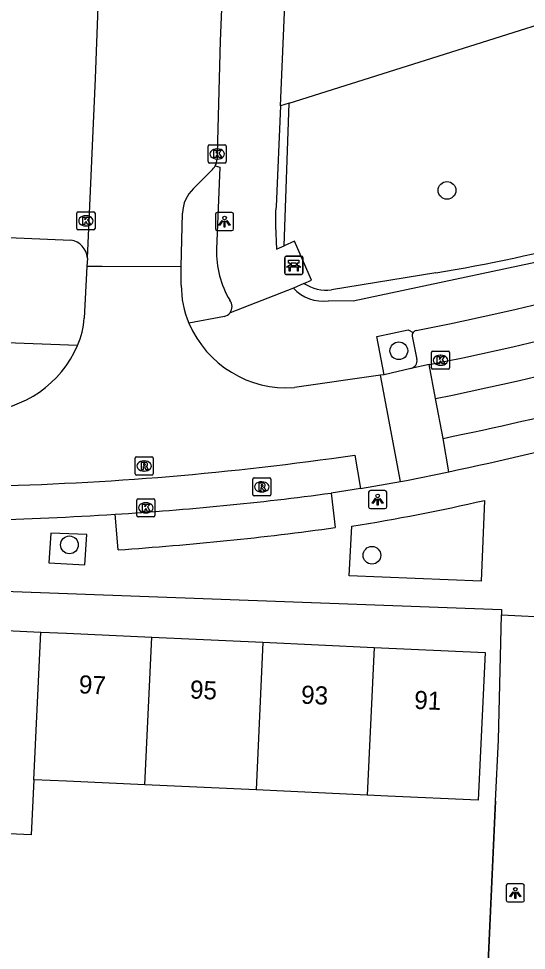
# Model space of a CAD drawing. Extents: x 161355 to 162026, y 386504 to 387459.
# Drawn here: x 161497.3 to 161525.4, y 386792.5 to 386843.9 of the extents above; entities that cross this region are included whole.
import ezdxf

# ---------------------------------------------------------------- set-up
doc = ezdxf.new("R2010")
doc.units = 0
for name, color, linetype in [('IMGEO_Bank', 7, 'Continuous'), ('IMGEO_Boom', 7, 'Continuous'), ('IMGEO_Groenvoorziening', 7, 'Continuous'), ('IMGEO_Haag', 7, 'Continuous'), ('IMGEO_Kolk', 7, 'Continuous'), ('IMGEO_Lichtpunt', 7, 'Continuous'), ('IMGEO_Muur', 7, 'Continuous'), ('IMGEO_Pand', 7, 'Continuous'), ('IMGEO_Pand_nummerreeks', 7, 'Continuous'), ('IMGEO_Parkeervlak_open', 7, 'Continuous'), ('IMGEO_Rijbaan_lokaal_gesloten', 7, 'Continuous'), ('IMGEO_Rijbaan_lokaal_open', 7, 'Continuous'), ('IMGEO_Rioolput', 7, 'Continuous'), ('IMGEO_Voetpad_open', 7, 'Continuous')]:
    doc.layers.add(name, color=color, linetype=linetype)

msp = doc.modelspace()

# ---------------------------------------------------------------- linework, layer by layer
at = {"layer": 'IMGEO_Bank'}
for p, q in [((161512.04, 386829.902), (161512.04, 386830.743)), ((161512.04, 386830.743), (161512.04, 386829.902)), ((161512.115, 386830.827), (161512.956, 386830.827)), ((161512.956, 386830.827), (161512.115, 386830.827)), ((161513.04, 386830.752), (161513.04, 386829.911)), ((161513.04, 386829.911), (161513.04, 386830.752)), ((161512.737, 386830.225), (161512.344, 386830.225)), ((161512.349, 386830.333), (161512.349, 386830.439)), ((161512.393, 386830.439), (161512.393, 386830.333)), ((161512.681, 386830.445), (161512.399, 386830.445)), ((161512.399, 386830.327), (161512.681, 386830.327)), ((161512.687, 386830.333), (161512.687, 386830.439)), ((161512.731, 386830.439), (161512.731, 386830.333)), ((161512.965, 386829.827), (161512.124, 386829.827)), ((161512.124, 386829.827), (161512.965, 386829.827))]:
    msp.add_line(p, q, dxfattribs=at)
for points in [[(161512.343, 386830.445), (161512.257, 386830.445), (161512.257, 386830.606), (161512.82, 386830.606), (161512.82, 386830.445), (161512.737, 386830.445)], [(161512.287, 386830.225), (161512.145, 386830.225), (161512.257, 386830.327), (161512.343, 386830.327)], [(161512.337, 386830.218), (161512.337, 386830.011), (161512.294, 386830.011), (161512.294, 386830.218)], [(161512.737, 386830.327), (161512.82, 386830.327), (161512.932, 386830.225), (161512.793, 386830.225)], [(161512.787, 386830.218), (161512.787, 386830.011), (161512.743, 386830.011), (161512.743, 386830.218)]]:
    msp.add_lwpolyline(points, dxfattribs=at)
for centre, radius, start, end in [((161512.118, 386830.749), 0.0779, 92.4484, 184.2845), ((161512.118, 386830.749), 0.0779, 92.4484, 184.2845), ((161512.962, 386830.749), 0.0779, 2.4484, 94.2845), ((161512.962, 386830.749), 0.0779, 2.4484, 94.2845), ((161512.287, 386830.218), 0.00671, 2.8957, 87.1043), ((161512.344, 386830.218), 0.00671, 92.8957, 177.1043), ((161512.342, 386830.438), 0.00671, 2.8957, 87.1043), ((161512.342, 386830.334), 0.00671, 272.8957, 357.1043), ((161512.399, 386830.438), 0.00671, 92.8957, 177.1043), ((161512.399, 386830.334), 0.00671, 182.8957, 267.1043), ((161512.681, 386830.438), 0.00671, 2.8957, 87.1043), ((161512.681, 386830.334), 0.00671, 272.8957, 357.1043), ((161512.738, 386830.438), 0.00671, 92.8957, 177.1043), ((161512.738, 386830.334), 0.00671, 182.8957, 267.1043), ((161512.736, 386830.218), 0.00671, 2.8957, 87.1043), ((161512.793, 386830.218), 0.00671, 92.8957, 177.1043), ((161512.118, 386829.905), 0.0779, 182.4484, 274.2845), ((161512.118, 386829.905), 0.0779, 182.4484, 274.2845), ((161512.962, 386829.905), 0.0779, 272.4484, 4.2845), ((161512.962, 386829.905), 0.0779, 272.4484, 4.2845)]:
    msp.add_arc(centre, radius, start, end, dxfattribs=at)
at = {"layer": 'IMGEO_Boom'}
for centre in [(161520.999, 386834.464), (161518.34, 386825.613), (161500.153, 386814.901), (161516.856, 386814.324)]:
    msp.add_circle(centre, 0.489, dxfattribs=at)
at = {"layer": 'IMGEO_Groenvoorziening'}
msp.add_lwpolyline([(161512.278, 386839.281), (161538.761, 386847.649), (161539.899, 386848.027)], dxfattribs=at)
at = {"layer": 'IMGEO_Haag'}
for points in [[(161512.278, 386839.281), (161511.8, 386839.13)], [(161512.001, 386831.405), (161512.278, 386839.281)], [(161520.374, 386829.914), (161514.63, 386828.974)]]:
    msp.add_lwpolyline(points, dxfattribs=at)
for centre, radius, start, end in [((161506.753, 386913.447), 84.637, 279.26136, 285.20102), ((161514.367, 386831.329), 2.369, 237.7468, 276.3626)]:
    msp.add_arc(centre, radius, start, end, dxfattribs=at)
at = {"layer": 'IMGEO_Kolk'}
for p, q in [((161507.814, 386836.05), (161507.814, 386836.902)), ((161507.889, 386836.976), (161508.741, 386836.976)), ((161508.302, 386836.756), (161508.327, 386836.756)), ((161508.815, 386836.902), (161508.815, 386836.05)), ((161508.741, 386835.976), (161507.889, 386835.976)), ((161508.325, 386836.196), (161508.3, 386836.196)), ((161500.565, 386832.357), (161500.565, 386833.209)), ((161500.64, 386833.283), (161501.492, 386833.283)), ((161501.566, 386833.209), (161501.566, 386832.357)), ((161501.053, 386833.063), (161501.078, 386833.063)), ((161501.492, 386832.283), (161500.64, 386832.283)), ((161501.076, 386832.503), (161501.051, 386832.503)), ((161520.138, 386824.663), (161520.138, 386825.515)), ((161520.213, 386825.589), (161521.065, 386825.589)), ((161521.139, 386825.515), (161521.139, 386824.663)), ((161520.626, 386825.369), (161520.651, 386825.369)), ((161521.065, 386824.589), (161520.213, 386824.589)), ((161520.649, 386824.809), (161520.624, 386824.809)), ((161503.87, 386816.519), (161503.87, 386817.371)), ((161503.945, 386817.445), (161504.797, 386817.445)), ((161504.358, 386817.225), (161504.383, 386817.225)), ((161504.871, 386817.371), (161504.871, 386816.519)), ((161504.797, 386816.445), (161503.945, 386816.445)), ((161504.381, 386816.665), (161504.356, 386816.665))]:
    msp.add_line(p, q, dxfattribs=at)
for points in [[(161507.814, 386836.05), (161507.814, 386836.902)], [(161507.889, 386836.976), (161508.741, 386836.976)], [(161508.815, 386836.902), (161508.815, 386836.05)], [(161508.135, 386836.676), (161508.258, 386836.676), (161508.258, 386836.525), (161508.388, 386836.676), (161508.552, 386836.676), (161508.406, 386836.525), (161508.559, 386836.276), (161508.407, 386836.276), (161508.322, 386836.44), (161508.258, 386836.373), (161508.258, 386836.276), (161508.135, 386836.276), (161508.135, 386836.676)], [(161508.741, 386835.976), (161507.889, 386835.976)], [(161500.565, 386832.357), (161500.565, 386833.209)], [(161500.64, 386833.283), (161501.492, 386833.283)], [(161501.566, 386833.209), (161501.566, 386832.357)], [(161500.886, 386832.983), (161501.009, 386832.983), (161501.009, 386832.832), (161501.139, 386832.983), (161501.303, 386832.983), (161501.157, 386832.832), (161501.31, 386832.583), (161501.158, 386832.583), (161501.073, 386832.747), (161501.009, 386832.68), (161501.009, 386832.583), (161500.886, 386832.583), (161500.886, 386832.983)], [(161501.492, 386832.283), (161500.64, 386832.283)], [(161520.138, 386824.663), (161520.138, 386825.515)], [(161520.213, 386825.589), (161521.065, 386825.589)], [(161521.139, 386825.515), (161521.139, 386824.663)], [(161520.459, 386825.289), (161520.582, 386825.289), (161520.582, 386825.138), (161520.712, 386825.289), (161520.876, 386825.289), (161520.73, 386825.138), (161520.883, 386824.889), (161520.731, 386824.889), (161520.646, 386825.053), (161520.582, 386824.986), (161520.582, 386824.889), (161520.459, 386824.889), (161520.459, 386825.289)], [(161521.065, 386824.589), (161520.213, 386824.589)], [(161503.87, 386816.519), (161503.87, 386817.371)], [(161503.945, 386817.445), (161504.797, 386817.445)], [(161504.871, 386817.371), (161504.871, 386816.519)], [(161504.191, 386817.145), (161504.314, 386817.145), (161504.314, 386816.994), (161504.444, 386817.145), (161504.608, 386817.145), (161504.462, 386816.994), (161504.615, 386816.745), (161504.463, 386816.745), (161504.378, 386816.909), (161504.314, 386816.842), (161504.314, 386816.745), (161504.191, 386816.745), (161504.191, 386817.145)], [(161504.797, 386816.445), (161503.945, 386816.445)]]:
    msp.add_lwpolyline(points, dxfattribs=at)
for centre, start, end in [((161507.891, 386836.9), 91.552, 178.448), ((161507.891, 386836.9), 91.552, 178.448), ((161508.739, 386836.9), 1.552, 88.448), ((161508.739, 386836.9), 1.552, 88.448), ((161507.891, 386836.052), 181.552, 268.448), ((161507.891, 386836.052), 181.552, 268.448), ((161508.739, 386836.052), 271.552, 358.448), ((161508.739, 386836.052), 271.552, 358.448), ((161500.642, 386833.207), 91.552, 178.448), ((161500.642, 386833.207), 91.552, 178.448), ((161501.49, 386833.207), 1.552, 88.448), ((161501.49, 386833.207), 1.552, 88.448), ((161500.642, 386832.359), 181.552, 268.448), ((161500.642, 386832.359), 181.552, 268.448), ((161501.49, 386832.359), 271.552, 358.448), ((161501.49, 386832.359), 271.552, 358.448), ((161520.215, 386825.513), 91.552, 178.448), ((161520.215, 386825.513), 91.552, 178.448), ((161521.063, 386825.513), 1.552, 88.448), ((161521.063, 386825.513), 1.552, 88.448), ((161520.215, 386824.665), 181.552, 268.448), ((161520.215, 386824.665), 181.552, 268.448), ((161521.063, 386824.665), 271.552, 358.448), ((161521.063, 386824.665), 271.552, 358.448), ((161503.947, 386817.369), 91.552, 178.448), ((161503.947, 386817.369), 91.552, 178.448), ((161504.795, 386817.369), 1.552, 88.448), ((161504.795, 386817.369), 1.552, 88.448), ((161503.947, 386816.521), 181.552, 268.448), ((161503.947, 386816.521), 181.552, 268.448), ((161504.795, 386816.521), 271.552, 358.448), ((161504.795, 386816.521), 271.552, 358.448)]:
    msp.add_arc(centre, 0.0765, start, end, dxfattribs=at)
for centre, major_axis, ratio, start_param, end_param in [((161508.301, 386836.476), (-0.387, 0.002), 0.722429, 4.712389, 7.853982), ((161508.326, 386836.476), (-0.39, 0.002), 0.717154, 1.570796, 4.712389), ((161501.052, 386832.783), (-0.387, 0.002), 0.722429, 4.712389, 7.853982), ((161501.077, 386832.783), (-0.39, 0.002), 0.717154, 1.570796, 4.712389), ((161520.625, 386825.089), (-0.387, 0.002), 0.722429, 4.712389, 7.853982), ((161520.65, 386825.089), (-0.39, 0.002), 0.717154, 1.570796, 4.712389), ((161504.357, 386816.945), (-0.387, 0.002), 0.722429, 4.712389, 7.853982), ((161504.382, 386816.945), (-0.39, 0.002), 0.717154, 1.570796, 4.712389)]:
    msp.add_ellipse(centre, major_axis=major_axis, ratio=ratio, start_param=start_param, end_param=end_param, dxfattribs=at)
at = {"layer": 'IMGEO_Lichtpunt'}
for p, q in [((161509.12, 386833.241), (161508.312, 386833.241)), ((161509.12, 386833.241), (161508.312, 386833.241)), ((161508.218, 386833.146), (161508.218, 386832.339)), ((161508.218, 386833.146), (161508.218, 386832.339)), ((161509.214, 386832.339), (161509.214, 386833.146)), ((161509.214, 386832.339), (161509.214, 386833.146)), ((161508.312, 386832.245), (161509.12, 386832.245)), ((161508.312, 386832.245), (161509.12, 386832.245)), ((161516.673, 386817.805), (161516.673, 386816.998)), ((161516.673, 386817.805), (161516.673, 386816.998)), ((161517.575, 386817.9), (161516.767, 386817.9)), ((161517.575, 386817.9), (161516.767, 386817.9)), ((161517.669, 386816.998), (161517.669, 386817.805)), ((161517.669, 386816.998), (161517.669, 386817.805)), ((161516.767, 386816.904), (161517.575, 386816.904)), ((161516.767, 386816.904), (161517.575, 386816.904)), ((161525.175, 386796.188), (161524.367, 386796.188)), ((161525.175, 386796.188), (161524.367, 386796.188)), ((161524.273, 386796.093), (161524.273, 386795.286)), ((161524.273, 386796.093), (161524.273, 386795.286)), ((161525.269, 386795.286), (161525.269, 386796.093)), ((161525.269, 386795.286), (161525.269, 386796.093)), ((161524.367, 386795.192), (161525.175, 386795.192)), ((161524.367, 386795.192), (161525.175, 386795.192))]:
    msp.add_line(p, q, dxfattribs=at)
for points in [[(161508.592, 386832.81), (161508.631, 386832.782), (161508.443, 386832.52), (161508.405, 386832.547), (161508.592, 386832.81)], [(161508.694, 386832.762), (161508.741, 386832.762), (161508.741, 386832.44), (161508.694, 386832.44), (161508.694, 386832.762)], [(161508.804, 386832.782), (161508.842, 386832.809), (161509.029, 386832.547), (161508.99, 386832.519), (161508.804, 386832.782)], [(161517.047, 386817.469), (161517.086, 386817.441), (161516.898, 386817.179), (161516.86, 386817.206), (161517.047, 386817.469)], [(161517.149, 386817.421), (161517.196, 386817.421), (161517.196, 386817.099), (161517.149, 386817.099), (161517.149, 386817.421)], [(161517.259, 386817.441), (161517.297, 386817.468), (161517.484, 386817.206), (161517.445, 386817.178), (161517.259, 386817.441)], [(161524.647, 386795.757), (161524.686, 386795.729), (161524.498, 386795.467), (161524.46, 386795.494), (161524.647, 386795.757)], [(161524.749, 386795.709), (161524.796, 386795.709), (161524.796, 386795.387), (161524.749, 386795.387), (161524.749, 386795.709)], [(161524.859, 386795.729), (161524.897, 386795.756), (161525.084, 386795.494), (161525.045, 386795.466), (161524.859, 386795.729)]]:
    msp.add_lwpolyline(points, dxfattribs=at)
for centre in [(161508.717, 386832.944), (161517.172, 386817.603), (161524.772, 386795.891)]:
    msp.add_circle(centre, 0.0994, dxfattribs=at)
for centre, start, end in [((161508.312, 386833.146), 90, 180), ((161508.312, 386833.146), 90, 180), ((161509.12, 386833.146), 0, 90), ((161509.12, 386833.146), 0, 90), ((161508.312, 386832.339), 180, 270), ((161508.312, 386832.339), 180, 270), ((161509.12, 386832.339), 270, 0), ((161509.12, 386832.339), 270, 360), ((161516.767, 386817.805), 90, 180), ((161516.767, 386817.805), 90, 180), ((161517.575, 386817.805), 0, 90), ((161517.575, 386817.805), 0, 90), ((161516.767, 386816.998), 180, 270), ((161516.767, 386816.998), 180, 270), ((161517.575, 386816.998), 270, 0), ((161517.575, 386816.998), 270, 360), ((161524.367, 386796.093), 90, 180), ((161524.367, 386796.093), 90, 180), ((161525.175, 386796.093), 0, 90), ((161525.175, 386796.093), 0, 90), ((161524.367, 386795.286), 180, 270), ((161524.367, 386795.286), 180, 270), ((161525.175, 386795.286), 270, 0), ((161525.175, 386795.286), 270, 360)]:
    msp.add_arc(centre, 0.0946, start, end, dxfattribs=at)
at = {"layer": 'IMGEO_Muur'}
msp.add_lwpolyline([(161523.683, 386800.76), (161523.16, 386789.429)], dxfattribs=at)
at = {"layer": 'IMGEO_Pand'}
for points in [[(161492.43, 386810.375), (161498.566, 386810.091)], [(161498.189, 386801.939), (161498.566, 386810.091)], [(161498.566, 386810.091), (161500, 386810.025), (161504.702, 386809.807)], [(161504.325, 386801.655), (161504.702, 386809.807)], [(161504.702, 386809.807), (161510.838, 386809.524)], [(161510.838, 386809.524), (161510.461, 386801.372)], [(161510.838, 386809.524), (161516.974, 386809.24)], [(161516.974, 386809.24), (161523.106, 386808.956), (161522.729, 386800.804), (161517.735, 386801.035), (161516.597, 386801.088)], [(161516.974, 386809.24), (161516.597, 386801.088)], [(161498.189, 386801.939), (161498.048, 386798.898), (161491.912, 386799.181)], [(161504.325, 386801.655), (161500, 386801.855), (161498.189, 386801.939)], [(161510.461, 386801.372), (161504.325, 386801.655)], [(161516.597, 386801.088), (161510.461, 386801.372)]]:
    msp.add_lwpolyline(points, dxfattribs=at)
at = {"layer": 'IMGEO_Parkeervlak_open'}
for points in [[(161495.485, 386831.914), (161500.23, 386831.711)], [(161519.079, 386826.412), (161519.342, 386825.137)]]:
    msp.add_lwpolyline(points, dxfattribs=at)
for centre, radius, start, end in [((161500.105, 386830.679), 1.039, 2.9742, 83.0884), ((161519.36, 386826.453), 0.283, 144.7696, 188.2177), ((161518.897, 386825.075), 0.449, 284.2793, 7.916)]:
    msp.add_arc(centre, radius, start, end, dxfattribs=at)
at = {"layer": 'IMGEO_Rijbaan_lokaal_gesloten'}
for points in [[(161520.368, 386822.982), (161520.018, 386824.846)], [(161521.099, 386818.935), (161520.791, 386820.779)], [(161516.217, 386818.005), (161514.61, 386817.76)]]:
    msp.add_lwpolyline(points, dxfattribs=at)
for centre, radius, start, end in [((161488.255, 386984.249), 162.536, 281.2692, 291.90897), ((161488.231, 386983.377), 163.583, 281.3297, 291.94879), ((161485.711, 386992.759), 175.521, 281.5288, 287.31954), ((161480.452, 387011.97), 197.268, 281.89109, 287.15674), ((161492.314, 386983.601), 167.333, 273.54943, 277.65689), ((161490.303, 387016.248), 200.042, 271.44792, 273.54546)]:
    msp.add_arc(centre, radius, start, end, dxfattribs=at)
at = {"layer": 'IMGEO_Rijbaan_lokaal_open'}
for points in [[(161501.143, 386830.733), (161501.602, 386840.641), (161502.894, 386875.753)], [(161508.658, 386847.12), (161508.474, 386842.71), (161508.315, 386836.476), (161508.312, 386836.198)], [(161506.999, 386834.57), (161508.002, 386835.57)], [(161506.315, 386830.237), (161506.39, 386833.21)], [(161501.143, 386830.733), (161501.115, 386830.263)], [(161501.115, 386830.263), (161500.973, 386827.416)], [(161506.315, 386830.237), (161501.963, 386830.261), (161501.115, 386830.263)], [(161506.329, 386829.238), (161506.315, 386830.237)], [(161519.008, 386824.64), (161517.535, 386824.294)], [(161520.018, 386824.846), (161519.008, 386824.64)], [(161517.334, 386824.272), (161512.575, 386823.583)], [(161517.535, 386824.294), (161517.334, 386824.272)], [(161518.426, 386818.391), (161517.334, 386824.272)], [(161520.791, 386820.779), (161520.368, 386822.982)], [(161515.906, 386819.854), (161516.217, 386818.005)], [(161518.426, 386818.391), (161518.758, 386818.449), (161521.099, 386818.935)], [(161516.217, 386818.005), (161518.426, 386818.391)]]:
    msp.add_lwpolyline(points, dxfattribs=at)
for centre, radius, start, end in [((161507.411, 386836.25), 0.901, 310.9812, 331.9179), ((161507.408, 386836.255), 0.906, 331.7724, 356.4182), ((161508.41, 386833.122), 2.022, 134.2553, 177.4996), ((161511.634, 386829.204), 5.305, 179.6378, 202.982), ((161496.689, 386827.659), 4.291, 335.7751, 356.7571), ((161512.15, 386829.439), 5.872, 203.1271, 274.1531), ((161495.009, 386828.348), 6.106, 273.2685, 336.3408), ((161491.827, 386984.539), 166.436, 271.22458, 278.31842)]:
    msp.add_arc(centre, radius, start, end, dxfattribs=at)
at = {"layer": 'IMGEO_Rioolput'}
for p, q in [((161503.776, 386818.829), (161503.776, 386819.681)), ((161503.851, 386819.755), (161504.703, 386819.755)), ((161504.264, 386819.535), (161504.289, 386819.535)), ((161504.777, 386819.681), (161504.777, 386818.829)), ((161504.703, 386818.755), (161503.851, 386818.755)), ((161504.287, 386818.975), (161504.262, 386818.975)), ((161510.272, 386817.674), (161510.272, 386818.526)), ((161510.347, 386818.6), (161511.199, 386818.6)), ((161510.76, 386818.38), (161510.785, 386818.38)), ((161511.273, 386818.526), (161511.273, 386817.674)), ((161510.783, 386817.82), (161510.758, 386817.82)), ((161511.199, 386817.6), (161510.347, 386817.6))]:
    msp.add_line(p, q, dxfattribs=at)
for points in [[(161503.776, 386818.829), (161503.776, 386819.681)], [(161503.851, 386819.755), (161504.703, 386819.755)], [(161504.365, 386819.453), (161504.113, 386819.455), (161504.113, 386819.055)], [(161504.291, 386819.374), (161504.237, 386819.374), (161504.237, 386819.293)], [(161504.237, 386819.293), (161504.289, 386819.293)], [(161504.777, 386819.681), (161504.777, 386818.829)], [(161504.703, 386818.755), (161503.851, 386818.755)], [(161504.113, 386819.055), (161504.237, 386819.055), (161504.237, 386819.217), (161504.248, 386819.217)], [(161504.295, 386819.188), (161504.366, 386819.055), (161504.506, 386819.055), (161504.441, 386819.181)], [(161510.272, 386817.674), (161510.272, 386818.526)], [(161510.347, 386818.6), (161511.199, 386818.6)], [(161510.861, 386818.298), (161510.609, 386818.3), (161510.609, 386817.9)], [(161511.273, 386818.526), (161511.273, 386817.674)], [(161510.609, 386817.9), (161510.733, 386817.9), (161510.733, 386818.062), (161510.744, 386818.062)], [(161510.787, 386818.219), (161510.733, 386818.219), (161510.733, 386818.138)], [(161510.733, 386818.138), (161510.785, 386818.138)], [(161510.791, 386818.033), (161510.862, 386817.9), (161511.002, 386817.9), (161510.937, 386818.026)], [(161511.199, 386817.6), (161510.347, 386817.6)]]:
    msp.add_lwpolyline(points, dxfattribs=at)
for centre, radius, start, end in [((161503.853, 386819.679), 0.0765, 91.552, 178.448), ((161503.853, 386819.679), 0.0765, 91.552, 178.448), ((161504.273, 386819.482), 0.19, 274.7715, 282.9687), ((161504.297, 386819.278), 0.0964, 77.0061, 93.1865), ((161504.311, 386819.335), 0.0378, 276.6634, 79.6772), ((161504.364, 386819.343), 0.109, 350.3612, 89.416), ((161504.362, 386819.343), 0.112, 277.5842, 350.9817), ((161504.701, 386819.679), 0.0765, 1.552, 88.448), ((161504.701, 386819.679), 0.0765, 1.552, 88.448), ((161503.853, 386818.831), 0.0765, 181.552, 268.448), ((161503.853, 386818.831), 0.0765, 181.552, 268.448), ((161504.247, 386819.164), 0.0533, 26.0293, 88.6989), ((161504.346, 386819.128), 0.108, 29.5134, 73.7905), ((161504.701, 386818.831), 0.0765, 271.552, 358.448), ((161504.701, 386818.831), 0.0765, 271.552, 358.448), ((161510.349, 386818.524), 0.0765, 91.552, 178.448), ((161510.349, 386818.524), 0.0765, 91.552, 178.448), ((161510.86, 386818.188), 0.109, 350.3612, 89.416), ((161511.197, 386818.524), 0.0765, 1.552, 88.448), ((161511.197, 386818.524), 0.0765, 1.552, 88.448), ((161510.743, 386818.009), 0.0533, 26.0293, 88.6989), ((161510.769, 386818.327), 0.19, 274.7715, 282.9687), ((161510.793, 386818.123), 0.0964, 77.0061, 93.1865), ((161510.807, 386818.18), 0.0378, 276.6634, 79.6772), ((161510.858, 386818.188), 0.112, 277.5842, 350.9817), ((161510.842, 386817.973), 0.108, 29.5134, 73.7905), ((161510.349, 386817.676), 0.0765, 181.552, 268.448), ((161510.349, 386817.676), 0.0765, 181.552, 268.448), ((161511.197, 386817.676), 0.0765, 271.552, 358.448), ((161511.197, 386817.676), 0.0765, 271.552, 358.448)]:
    msp.add_arc(centre, radius, start, end, dxfattribs=at)
for centre, major_axis, ratio, start_param, end_param in [((161504.263, 386819.255), (-0.387, 0.002), 0.722429, 4.712389, 7.853982), ((161504.288, 386819.255), (-0.39, 0.002), 0.717154, 1.570796, 4.712389), ((161510.759, 386818.1), (-0.387, 0.002), 0.722429, 4.712389, 7.853982), ((161510.784, 386818.1), (-0.39, 0.002), 0.717154, 1.570796, 4.712389)]:
    msp.add_ellipse(centre, major_axis=major_axis, ratio=ratio, start_param=start_param, end_param=end_param, dxfattribs=at)
at = {"layer": 'IMGEO_Voetpad_open'}
for points in [[(161511.8, 386839.13), (161513.476, 386878.267)], [(161545.191, 386839.884), (161543.789, 386836.438), (161541.337, 386835.451), (161537.295, 386833.825), (161536.546, 386833.523), (161529.161, 386831.19), (161515.819, 386828.343), (161514.452, 386828.372)], [(161511.8, 386839.13), (161511.562, 386833.581)], [(161508.206, 386835.826), (161508.464, 386835.753), (161508.265, 386831.216)], [(161511.539, 386832.502), (161511.587, 386831.224), (161511.756, 386831.298), (161512.001, 386831.405)], [(161513.103, 386829.325), (161513.523, 386829.505), (161512.578, 386831.657), (161512.001, 386831.405)], [(161512.522, 386829.076), (161509.02, 386827.712)], [(161513.103, 386829.325), (161512.522, 386829.076)], [(161508.706, 386827.502), (161506.75, 386827.133)], [(161517.535, 386824.294), (161517.122, 386826.408), (161518.848, 386826.777), (161519.128, 386826.616)], [(161500.602, 386825.898), (161495.677, 386826.081)], [(161514.61, 386817.76), (161514.833, 386815.853)], [(161523.061, 386817.353), (161522.888, 386812.892), (161515.592, 386813.19), (161515.738, 386815.931)], [(161502.851, 386814.628), (161502.674, 386816.589)], [(161501.013, 386813.794), (161501.109, 386815.467), (161499.12, 386815.552), (161499.016, 386813.902), (161501.013, 386813.794)], [(161492.529, 386812.499), (161524.007, 386811.339), (161524, 386811.032)], [(161523.04, 386786.822), (161523.16, 386789.429), (161523.683, 386800.76), (161523.839, 386804.137), (161524, 386811.032)], [(161524, 386811.032), (161526.977, 386810.897)]]:
    msp.add_lwpolyline(points, dxfattribs=at)
for centre, radius, start, end in [((161489.01, 386981.291), 157.5, 281.08766, 292.05075), ((161517.846, 386832.907), 6.32, 173.8805, 183.6772), ((161513.72, 386831.15), 5.456, 179.304, 210.3032), ((161514.149, 386830.539), 2.188, 221.9545, 277.9649), ((161508.567, 386828.048), 0.564, 323.4162, 38.2566), ((161508.566, 386828.05), 0.566, 284.2771, 323.2714), ((161519.367, 386826.446), 0.293, 103.325, 144.5178), ((161498.28, 386925.403), 110.855, 279.06092, 282.91726), ((161491.142, 386988.37), 174.136, 273.85556, 277.81933)]:
    msp.add_arc(centre, radius, start, end, dxfattribs=at)

# ---------------------------------------------------------------- texts
at = {"layer": 'IMGEO_Pand_nummerreeks'}
for s, p in [('97', (161500.656, 386806.71)), ('95', (161506.791, 386806.427)), ('93', (161512.926, 386806.143)), ('91', (161519.174, 386805.854))]:
    msp.add_text(s, height=1, rotation=357.3515, dxfattribs=at).set_placement(p)

doc.saveas('drawing.dxf')
